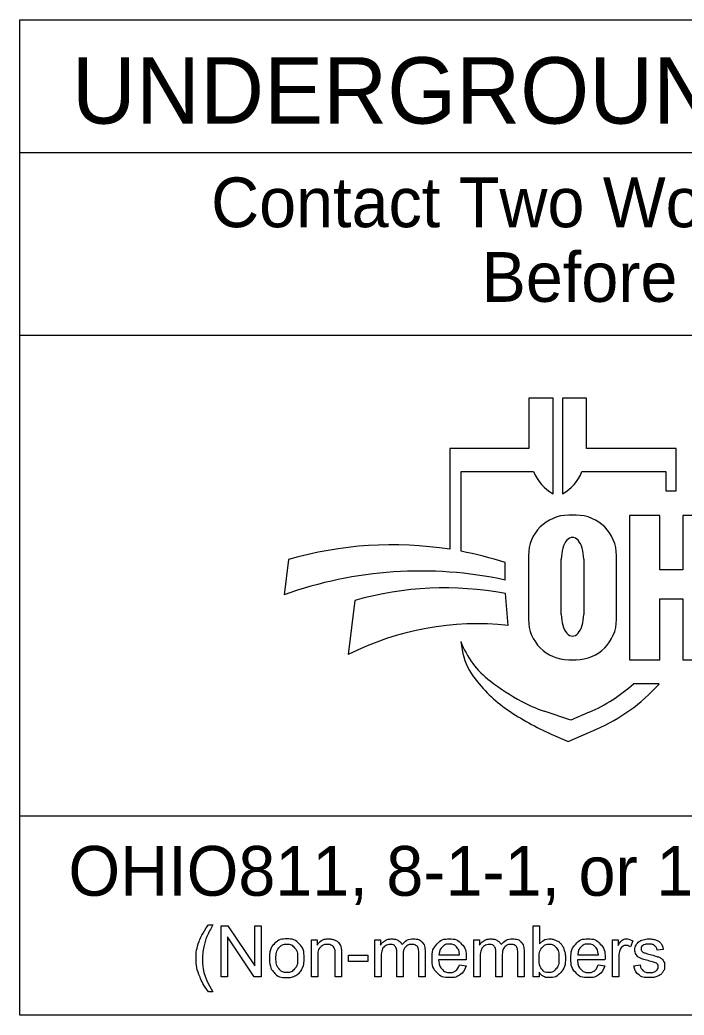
# Model space of a CAD drawing. Extents: x 0 to 34, y 0 to 22.
# Drawn here: x 3.25 to 5.253, y 2.257 to 5.257 of the extents above; entities that cross this region are included whole.
import ezdxf

# ---------------------------------------------------------------- set-up
doc = ezdxf.new("R2010")
doc.units = 0
doc.layers.add('SH_Data', color=7, linetype='Continuous')

msp = doc.modelspace()

# ---------------------------------------------------------------- linework, layer by layer
at = {"layer": 'SH_Data'}
for p, q in [((3.25, 5.2574), (8, 5.2574)), ((3.25, 2.2574), (3.25, 5.2574)), ((3.25, 4.8574), (8, 4.8574)), ((3.25, 4.3074), (8, 4.3074)), ((4.8581, 4.1169), (4.7853, 4.1169)), ((4.7853, 4.1169), (4.7853, 3.9655)), ((4.8581, 3.8289), (4.8581, 4.1169)), ((4.9592, 4.1169), (4.8864, 4.1169)), ((4.8864, 4.1169), (4.8864, 3.8289)), ((4.9592, 3.9655), (4.9592, 4.1169)), ((4.7853, 3.9655), (4.5463, 3.9655)), ((4.5463, 3.9655), (4.5463, 3.6615)), ((5.2298, 3.9655), (4.9592, 3.9655)), ((5.2298, 3.8381), (5.2298, 3.9655)), ((4.5806, 3.6555), (4.5806, 3.8957)), ((4.5806, 3.8957), (4.7994, 3.8957)), ((4.9451, 3.8957), (5.1982, 3.8957)), ((5.1982, 3.8957), (5.1982, 3.8381)), ((5.1982, 3.8381), (5.2298, 3.8381)), ((4.9279, 3.7644), (4.9054, 3.7644)), ((5.1805, 3.7631), (5.0882, 3.7631)), ((5.0882, 3.7631), (5.0882, 3.3286)), ((4.0599, 3.6304), (4.0472, 3.5243)), ((4.7839, 3.6429), (4.7839, 3.4501)), ((4.8829, 3.4655), (4.8829, 3.6317)), ((4.9505, 3.6317), (4.9505, 3.4655)), ((5.0494, 3.4501), (5.0494, 3.6429)), ((4.7135, 3.5688), (4.7135, 3.6216)), ((4.7227, 3.432), (4.7142, 3.5284)), ((5.1805, 3.3286), (5.1805, 3.5123)), ((4.2605, 3.5074), (4.2405, 3.3443)), ((4.5797, 3.3832), (4.5839, 3.3589)), ((4.9054, 3.3286), (4.9279, 3.3286)), ((5.0882, 3.3286), (5.1805, 3.3286)), ((5.1783, 3.2558), (5.1003, 3.2558)), ((5.1761, 3.2534), (5.1783, 3.2558)), ((4.9116, 3.146), (4.8309, 3.1738)), ((4.9673, 3.1702), (4.9116, 3.146)), ((4.8527, 3.1045), (4.9034, 3.0822)), ((4.9034, 3.0822), (4.9893, 3.1195)), ((8, 2.8574), (3.25, 2.8574)), ((8, 2.2574), (3.25, 2.2574))]:
    msp.add_line(p, q, dxfattribs=at)
for points in [[(5.1805, 3.5123), (5.2497, 3.5123), (5.2497, 3.3286), (5.342, 3.3286), (5.342, 3.7631), (5.2497, 3.7631), (5.2497, 3.5992), (5.1805, 3.5992), (5.1805, 3.7631)], [(3.8189, 2.5293), (3.8324, 2.5293)], [(3.8566, 2.3728), (3.8566, 2.5268), (3.8775, 2.5268), (3.9585, 2.4058), (3.9585, 2.5268), (3.978, 2.5268), (3.978, 2.3728), (3.9571, 2.3728), (3.8761, 2.4937), (3.8761, 2.3728), (3.8566, 2.3728)], [(4.8161, 2.3728), (4.7986, 2.3728), (4.7986, 2.5268), (4.8175, 2.5268), (4.8175, 2.4719)], [(4.1294, 2.3728), (4.1294, 2.4844), (4.1464, 2.4844), (4.1464, 2.4685)], [(4.3206, 2.3728), (4.3206, 2.4844), (4.3375, 2.4844), (4.3375, 2.4686)], [(4.6194, 2.3728), (4.6194, 2.4844), (4.6363, 2.4844), (4.6363, 2.4686)], [(5.0377, 2.3728), (5.0377, 2.4844), (5.0547, 2.4844), (5.0547, 2.4675)], [(5.0982, 2.4808), (5.0916, 2.4633)], [(4.1483, 2.4337), (4.1483, 2.3728), (4.1294, 2.3728)], [(4.22, 2.4414), (4.22, 2.3728), (4.2011, 2.3728), (4.2011, 2.4406)], [(4.2415, 2.419), (4.2415, 2.438), (4.2997, 2.438), (4.2997, 2.419), (4.2415, 2.419)], [(4.3395, 2.4306), (4.3395, 2.3728), (4.3206, 2.3728)], [(4.4058, 2.4376), (4.4058, 2.3728), (4.3869, 2.3728), (4.3869, 2.4452)], [(4.4719, 2.4493), (4.4719, 2.3728), (4.453, 2.3728), (4.453, 2.443)], [(4.514, 2.4392), (4.5764, 2.4392)], [(4.6383, 2.4306), (4.6383, 2.3728), (4.6194, 2.3728)], [(4.7047, 2.4376), (4.7047, 2.3728), (4.6858, 2.3728), (4.6858, 2.4452)], [(4.7707, 2.4493), (4.7707, 2.3728), (4.7518, 2.3728), (4.7518, 2.443)], [(4.9325, 2.4392), (4.9948, 2.4392)], [(5.0566, 2.4312), (5.0566, 2.3728), (5.0377, 2.3728)], [(5.1905, 2.4555), (5.172, 2.453)], [(4.5962, 2.4237), (4.513, 2.4237)], [(4.5762, 2.4088), (4.5957, 2.4063)], [(5.0147, 2.4237), (4.9314, 2.4237)], [(4.9946, 2.4088), (5.0142, 2.4063)], [(5.1019, 2.4061), (5.1205, 2.409)], [(4.8161, 2.3867), (4.8161, 2.3728)], [(3.8324, 2.3275), (3.8189, 2.3275)]]:
    msp.add_lwpolyline(points, dxfattribs=at)
for centre, radius, start, end in [((4.9235, 3.9456), 0.1337, 201.9296, 240.7469), ((4.8211, 3.9456), 0.1337, 299.2531, 338.0704), ((4.9054, 3.6429), 0.1215, 90, 180), ((4.9279, 3.6429), 0.1215, 0, 90), ((4.3724, 2.5629), 1.1123, 81.0007, 106.3144), ((4.3724, 2.5629), 1.1123, 72.1402, 79.2074), ((4.458, 2.3848), 1.2113, 77.8238, 109.8274), ((4.532, 2.5509), 0.9943, 79.44, 105.8467), ((4.9054, 3.4501), 0.1215, 180, 270), ((4.9279, 3.4501), 0.1215, 270, 0), ((4.6298, 2.5737), 0.8633, 83.8248, 116.8021), ((4.8342, 3.4811), 0.2727, 201.0457, 232.5314), ((4.7758, 3.3916), 0.1947, 189.6817, 216.0884), ((4.9573, 3.5239), 0.4193, 216.0884, 235.7167), ((5.0957, 3.8223), 0.7025, 232.5314, 241.794), ((4.7725, 3.619), 0.4892, 293.4582, 312.0712), ((4.7725, 3.619), 0.5445, 293.4582, 317.8286), ((4.98, 3.6066), 0.4578, 241.794, 250.9821), ((5.1834, 3.8556), 0.8207, 235.7167, 246.2325)]:
    msp.add_arc(centre, radius, start, end, dxfattribs=at)
for centre, start_param, end_param in [((4.9167, 3.6317), 4.712389, 7.853982), ((4.9167, 3.4655), 1.570796, 4.712389)]:
    msp.add_ellipse(centre, major_axis=(0, 0.0657), ratio=0.514403, start_param=start_param, end_param=end_param, dxfattribs=at)
for points in [[(3.8189, 2.3275), (3.8033, 2.3472), (3.7924, 2.3737), (3.7816, 2.4001), (3.7816, 2.4285), (3.7816, 2.4535), (3.7897, 2.4764), (3.7992, 2.503), (3.8189, 2.5293)], [(3.8324, 2.5293), (3.8198, 2.5075), (3.8157, 2.4981), (3.8093, 2.4836), (3.8056, 2.4679), (3.8011, 2.4483), (3.8011, 2.4284), (3.8011, 2.3779), (3.8324, 2.3275)], [(4.0028, 2.4286), (4.0028, 2.4595), (4.02, 2.4745), (4.0344, 2.4869), (4.055, 2.4869), (4.078, 2.4869), (4.0926, 2.4718), (4.1072, 2.4567), (4.1072, 2.4301), (4.1072, 2.4086), (4.1008, 2.3963), (4.0943, 2.3839), (4.082, 2.3771), (4.0696, 2.3703), (4.055, 2.3703), (4.0316, 2.3703), (4.0172, 2.3853), (4.0028, 2.4003), (4.0028, 2.4286)], [(4.0222, 2.4286), (4.0222, 2.4071), (4.0316, 2.3965), (4.0409, 2.3858), (4.055, 2.3858), (4.0691, 2.3858), (4.0784, 2.3965), (4.0877, 2.4072), (4.0877, 2.4292), (4.0877, 2.4499), (4.0784, 2.4606), (4.069, 2.4712), (4.055, 2.4712), (4.0409, 2.4712), (4.0316, 2.4606), (4.0222, 2.45), (4.0222, 2.4286)], [(4.1464, 2.4685), (4.1587, 2.4869), (4.1819, 2.4869), (4.192, 2.4869), (4.2004, 2.4832), (4.2089, 2.4796), (4.2131, 2.4737), (4.2173, 2.4678), (4.219, 2.4597), (4.22, 2.4545), (4.22, 2.4414)], [(4.2011, 2.4406), (4.2011, 2.4521), (4.1989, 2.4579), (4.1967, 2.4636), (4.1911, 2.467), (4.1855, 2.4704), (4.1779, 2.4704), (4.1658, 2.4704), (4.1571, 2.4628), (4.1483, 2.4551), (4.1483, 2.4337)], [(4.3375, 2.4686), (4.3427, 2.4768), (4.3515, 2.4818), (4.3602, 2.4869), (4.3713, 2.4869), (4.3837, 2.4869), (4.3917, 2.4817), (4.3996, 2.4765), (4.4029, 2.4673), (4.4161, 2.4869), (4.4374, 2.4869), (4.454, 2.4869), (4.4629, 2.4777), (4.4719, 2.4685), (4.4719, 2.4493)], [(4.3869, 2.4452), (4.3869, 2.4578), (4.3823, 2.4641), (4.3777, 2.4704), (4.3671, 2.4704), (4.3592, 2.4704), (4.3524, 2.4662), (4.3456, 2.462), (4.3425, 2.4539), (4.3395, 2.4458), (4.3395, 2.4306)], [(4.453, 2.443), (4.453, 2.4544), (4.4512, 2.4593), (4.4493, 2.4643), (4.4445, 2.4674), (4.4396, 2.4704), (4.4331, 2.4704), (4.4214, 2.4704), (4.4136, 2.4626), (4.4058, 2.4548), (4.4058, 2.4376)], [(4.5957, 2.4063), (4.5911, 2.3892), (4.5786, 2.3797), (4.5661, 2.3703), (4.5467, 2.3703), (4.5222, 2.3703), (4.5078, 2.3854), (4.4935, 2.4004), (4.4935, 2.4276), (4.4935, 2.4558), (4.508, 2.4713), (4.5225, 2.4869), (4.5456, 2.4869), (4.568, 2.4869), (4.5822, 2.4716), (4.5963, 2.4564), (4.5963, 2.4287), (4.5963, 2.4271), (4.5962, 2.4237)], [(4.5764, 2.4392), (4.5751, 2.4533), (4.5692, 2.4604), (4.5602, 2.4714), (4.5458, 2.4714), (4.5328, 2.4714), (4.5239, 2.4626), (4.515, 2.4539), (4.514, 2.4392)], [(4.6363, 2.4686), (4.6416, 2.4768), (4.6503, 2.4818), (4.659, 2.4869), (4.6702, 2.4869), (4.6826, 2.4869), (4.6905, 2.4817), (4.6985, 2.4765), (4.7017, 2.4673), (4.715, 2.4869), (4.7362, 2.4869), (4.7528, 2.4869), (4.7618, 2.4777), (4.7707, 2.4685), (4.7707, 2.4493)], [(4.6858, 2.4452), (4.6858, 2.4578), (4.6811, 2.4641), (4.6765, 2.4704), (4.666, 2.4704), (4.658, 2.4704), (4.6512, 2.4662), (4.6444, 2.462), (4.6414, 2.4539), (4.6383, 2.4458), (4.6383, 2.4306)], [(4.7518, 2.443), (4.7518, 2.4544), (4.75, 2.4593), (4.7482, 2.4643), (4.7433, 2.4674), (4.7385, 2.4704), (4.732, 2.4704), (4.7202, 2.4704), (4.7124, 2.4626), (4.7047, 2.4548), (4.7047, 2.4376)], [(4.8158, 2.4294), (4.8158, 2.4093), (4.8213, 2.4004), (4.8302, 2.3858), (4.8454, 2.3858), (4.8578, 2.3858), (4.8668, 2.3966), (4.8758, 2.4073), (4.8758, 2.4287), (4.8758, 2.4505), (4.8672, 2.4609), (4.8585, 2.4714), (4.8462, 2.4714), (4.8339, 2.4714), (4.8248, 2.4606), (4.8158, 2.4498), (4.8158, 2.4294)], [(4.8175, 2.4719), (4.8294, 2.4869), (4.848, 2.4869), (4.8583, 2.4869), (4.8675, 2.4827), (4.8767, 2.4786), (4.8826, 2.471), (4.8886, 2.4635), (4.8919, 2.4529), (4.8953, 2.4423), (4.8953, 2.4303), (4.8953, 2.4016), (4.8811, 2.3859), (4.8669, 2.3703), (4.8471, 2.3703), (4.8273, 2.3703), (4.8161, 2.3867)], [(5.0142, 2.4063), (5.0095, 2.3892), (4.997, 2.3797), (4.9845, 2.3703), (4.9651, 2.3703), (4.9406, 2.3703), (4.9263, 2.3854), (4.912, 2.4004), (4.912, 2.4276), (4.912, 2.4558), (4.9265, 2.4713), (4.9409, 2.4869), (4.9641, 2.4869), (4.9864, 2.4869), (5.0006, 2.4716), (5.0148, 2.4564), (5.0148, 2.4287), (5.0148, 2.4271), (5.0147, 2.4237)], [(4.9948, 2.4392), (4.9936, 2.4533), (4.9877, 2.4604), (4.9786, 2.4714), (4.9642, 2.4714), (4.9512, 2.4714), (4.9423, 2.4626), (4.9334, 2.4539), (4.9325, 2.4392)], [(5.0547, 2.4675), (5.0612, 2.4793), (5.0667, 2.4831), (5.0722, 2.4869), (5.0788, 2.4869), (5.0884, 2.4869), (5.0982, 2.4808)], [(5.0916, 2.4633), (5.0847, 2.4674), (5.0778, 2.4674), (5.0716, 2.4674), (5.0667, 2.4636), (5.0618, 2.4599), (5.0597, 2.4533), (5.0566, 2.4432), (5.0566, 2.4312)], [(5.172, 2.453), (5.1707, 2.4617), (5.1646, 2.4665), (5.1586, 2.4714), (5.1476, 2.4714), (5.1345, 2.4714), (5.1289, 2.467), (5.1234, 2.4627), (5.1234, 2.4569), (5.1234, 2.4533), (5.1257, 2.4503), (5.128, 2.4473), (5.1329, 2.4453), (5.1358, 2.4442), (5.1497, 2.4404), (5.1697, 2.4351), (5.1777, 2.4317), (5.1857, 2.4282), (5.1902, 2.4217), (5.1947, 2.4152), (5.1947, 2.4056), (5.1947, 2.3961), (5.1892, 2.3878), (5.1837, 2.3794), (5.1732, 2.3749), (5.1628, 2.3703), (5.1497, 2.3703), (5.1279, 2.3703), (5.1165, 2.3793), (5.105, 2.3884), (5.1019, 2.4061)], [(5.1205, 2.409), (5.1221, 2.3978), (5.1293, 2.3918), (5.1366, 2.3858), (5.1495, 2.3858), (5.1626, 2.3858), (5.1689, 2.3911), (5.1752, 2.3964), (5.1752, 2.4036), (5.1752, 2.41), (5.1696, 2.4137), (5.1657, 2.4162), (5.1503, 2.4201), (5.1295, 2.4253), (5.1214, 2.4292), (5.1134, 2.433), (5.1092, 2.4398), (5.105, 2.4465), (5.105, 2.4547), (5.105, 2.4622), (5.1085, 2.4685), (5.1119, 2.4749), (5.1178, 2.4791), (5.1222, 2.4823), (5.1298, 2.4846), (5.1375, 2.4869), (5.1462, 2.4869), (5.1593, 2.4869), (5.1693, 2.4831), (5.1792, 2.4793), (5.184, 2.4728), (5.1887, 2.4663), (5.1905, 2.4555)], [(4.513, 2.4237), (4.514, 2.4053), (4.5234, 2.3956), (4.5328, 2.3858), (4.5467, 2.3858), (4.5571, 2.3858), (4.5645, 2.3913), (4.5719, 2.3968), (4.5762, 2.4088)], [(4.9314, 2.4237), (4.9325, 2.4053), (4.9419, 2.3956), (4.9512, 2.3858), (4.9652, 2.3858), (4.9756, 2.3858), (4.983, 2.3913), (4.9903, 2.3968), (4.9946, 2.4088)]]:
    msp.add_open_spline(points, degree=3, dxfattribs=at)

# ---------------------------------------------------------------- texts
for s, height, p in [('UNDERGROUND UTILITIES', 0.2, (3.4069, 4.9448)), ('Contact Two Working Days', 0.15, (3.8267, 4.6325)), ('Before You Dig', 0.15, (4.6423, 4.4075)), ('OHIO811, 8-1-1, or 1-800-362-2764', 0.15, (3.3964, 2.6172))]:
    msp.add_text(s, height=height, dxfattribs=at).set_placement(p)

doc.saveas('drawing.dxf')
